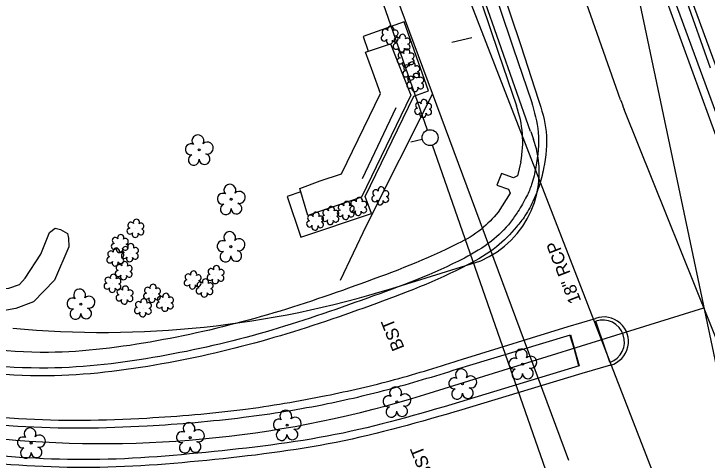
# Model space of a CAD drawing. Extents: x 1611576 to 1617186, y 899279 to 905462.
# Drawn here: x 1615954.6 to 1616172.8, y 904028.8 to 904169.2 of the extents above; entities that cross this region are included whole.
import ezdxf

# ---------------------------------------------------------------- set-up
doc = ezdxf.new("R2010")
doc.units = 0
for name, color, linetype in [('Default', 7, 'Continuous'), ('Exist Building', 7, 'Continuous'), ('Exist Horizontal Alignment', 7, 'Continuous'), ('Exist Other Culture Sign', 7, 'Continuous'), ('Exist Right of Way Line', 7, 'Continuous'), ('Exist Roads Curbs', 7, 'Continuous'), ('Exist Roads EOP', 7, 'Continuous'), ('Exist Roads EOP Other', 7, 'Continuous'), ('Exist Roads EOP Text', 7, 'Continuous'), ('Exist Structure Minor Pipes RCP 18 Inch', 7, 'Continuous'), ('Exist Structure Minor Pipes RCP 18 Inch Text', 7, 'Continuous'), ('Exist Vegetation Hedge Row', 7, 'Continuous'), ('Exist Vegetation Shrub CELL', 7, 'Continuous'), ('Exist Vegetation Tree CELL', 7, 'Continuous'), ('Prop 2 In Gas Line (St)', 7, 'Continuous'), ('Prop 6 In Gas Line (B2)', 7, 'Continuous'), ('Prop OH Pow Tel CATV Lines', 7, 'Continuous')]:
    doc.layers.add(name, color=color, linetype=linetype)

msp = doc.modelspace()

# ---------------------------------------------------------------- linework, layer by layer
at = {"layer": 'Default'}
msp.add_line((1616083.13, 904129.72), (1616079.48, 904128.88), dxfattribs=at)
msp.add_circle((1616085.57, 904130.27), 2.5, dxfattribs=at)
at = {"layer": 'Exist Building'}
msp.add_lwpolyline([(1616044.92, 904113.19), (1616040.56, 904111.77), (1616044.91, 904098.91), (1616067.1, 904106.39), (1616065.17, 904111.75), (1616080.46, 904143.28), (1616085.08, 904145.04), (1616077.43, 904166.71), (1616064.56, 904162.08), (1616066.07, 904157.45)], dxfattribs=at)
msp.add_lwpolyline([(1616044.58, 904114.3), (1616050.95, 904116.67), (1616057.75, 904118.84), (1616069.94, 904144.16), (1616067.54, 904150.85), (1616065.21, 904157.16), (1616073.11, 904159.81), (1616079.51, 904143.63), (1616063.97, 904111.54), (1616047.14, 904105.79)], close=True, dxfattribs=at)
at = {"layer": 'Exist Horizontal Alignment'}
for p, q in [((1616145.53, 904142.15), (1616079.93, 904328.43)), ((1616182.78, 904049.14), (1616146.69, 904139.07)), ((1616083.93, 904049.4), (1616171.72, 904076.69))]:
    msp.add_line(p, q, dxfattribs=at)
for centre, radius, start, end in [((1616217.59, 904167.52), 76.39, 199.4, 201.8667), ((1615982.39, 904376.05), 342.06, 264.7333, 287.2667)]:
    msp.add_arc(centre, radius, start, end, dxfattribs=at)
at = {"layer": 'Exist Other Culture Sign'}
for p, q in [((1616098.75, 904161.67), (1616092.45, 904160.16)), ((1616064.32, 904117.42), (1616074.94, 904139.75))]:
    msp.add_line(p, q, dxfattribs=at)
at = {"layer": 'Exist Right of Way Line'}
for p, q in [((1615887.44, 905426.15), (1616864.55, 900788.06)), ((1616173.83, 904152.11), (1616108.23, 904338.4)), ((1616117.23, 904132.18), (1616051.63, 904318.47)), ((1616073.54, 904082.82), (1616101.55, 904091.53))]:
    msp.add_line(p, q, dxfattribs=at)
for centre, radius, start, end in [((1616217.59, 904167.52), 106.39, 199.4, 200.861), ((1616089.66, 904119.39), 30.29, 293.1066, 19.7584), ((1615982.39, 904376.05), 307.06, 264.7333, 287.2667)]:
    msp.add_arc(centre, radius, start, end, dxfattribs=at)
at = {"layer": 'Exist Roads Curbs'}
msp.add_line((1616138.89, 904069.09), (1616137.75, 904072.51), dxfattribs=at)
for points in [[(1616117.86, 904294.32), (1616132.6, 904254.66), (1616147.03, 904215.59), (1616161.55, 904176.09), (1616175.82, 904137.25), (1616190.47, 904097.09), (1616204.98, 904057.33), (1616219.73, 904016.73), (1616233.88, 903976.63), (1616247.93, 903936.53), (1616261.75, 903896.6), (1616275.82, 903856.12), (1616289.5, 903816.57), (1616303.58, 903775.98), (1616318, 903734.48)], [(1616071.77, 904277.47), (1616085.18, 904237.58), (1616098.48, 904197.94), (1616111.7, 904158.5), (1616117.5, 904141.64)], [(1616142.11, 904059.56), (1616140.07, 904065.79), (1616138.89, 904069.09)], [(1616097, 904058.32), (1616129.81, 904068.25), (1616132.47, 904058.42), (1616097.28, 904047.76)]]:
    msp.add_lwpolyline(points, dxfattribs=at)
msp.add_ellipse((1616139.92, 904066.03), major_axis=(-0.95, 6.77), ratio=0.999591, start_param=3.328084, end_param=6.467483, dxfattribs=at)
for points in [[(1616117.5, 904141.64), (1616119.61, 904131.89), (1616118.86, 904120.99), (1616117.54, 904115.53), (1616115.97, 904111.79), (1616113.21, 904107), (1616110.89, 904103.69), (1616104.9, 904097.71), (1616096.36, 904092.38), (1616065.87, 904079.76), (1616033.72, 904069.07), (1616000.54, 904061.43), (1615965.3, 904057.76), (1615923.02, 904061.54), (1615919.54, 904062.14), (1615912.5, 904064.32), (1615906.06, 904068.89), (1615903.75, 904071.29), (1615901.6, 904074.35), (1615899.43, 904079.59), (1615898.96, 904087.08)], [(1615933.45, 904041.7), (1615955.8, 904039.5), (1615996.5, 904039.58), (1616026.82, 904042.27), (1616053.3, 904046.56), (1616074.92, 904051.74), (1616097, 904058.32)], [(1616097.28, 904047.76), (1616058.24, 904037.32), (1616017.59, 904031.47), (1615976.53, 904028.93), (1615936.16, 904031.22)]]:
    msp.add_spline(points, degree=3, dxfattribs=at)
at = {"layer": 'Exist Roads EOP'}
for p, q in [((1616129.02, 904070.85), (1616137.63, 904073.36)), ((1616095.78, 904060.53), (1616129.02, 904070.85)), ((1616142.39, 904058.67), (1616133.32, 904056.07)), ((1616133.32, 904056.07), (1616097.99, 904045.33))]:
    msp.add_line(p, q, dxfattribs=at)
for points in [[(1616115.61, 904293.45), (1616130.22, 904253.88), (1616144.71, 904214.78), (1616159.36, 904175.17), (1616173.54, 904136.33), (1616188.19, 904096.22), (1616202.56, 904056.51), (1616217.36, 904015.9), (1616231.52, 903975.89), (1616245.62, 903935.7), (1616259.38, 903895.73), (1616273.35, 903855.36), (1616287.12, 903815.79), (1616301.21, 903775.08), (1616315.66, 903733.58)], [(1616115.61, 904293.45), (1616130.22, 904253.88), (1616144.71, 904214.78), (1616159.36, 904175.17), (1616173.54, 904136.33), (1616188.19, 904096.22), (1616202.56, 904056.51), (1616217.36, 904015.9), (1616231.52, 903975.89), (1616245.62, 903935.7), (1616259.38, 903895.73), (1616273.35, 903855.36), (1616287.12, 903815.79)], [(1616074.22, 904278.19), (1616087.6, 904238.34), (1616100.83, 904198.88), (1616114.11, 904159.22), (1616119.62, 904142.34)]]:
    msp.add_lwpolyline(points, dxfattribs=at)
msp.add_ellipse((1616140.3, 904066.11), major_axis=(-0.84, 7.68), ratio=0.999926, start_param=3.305414, end_param=6.526886, dxfattribs=at)
for points in [[(1616119.62, 904142.34), (1616122.11, 904132.17), (1616121.32, 904120.53), (1616119.78, 904114.71), (1616118.22, 904110.85), (1616115.45, 904105.64), (1616112.79, 904102.18), (1616106.49, 904095.88), (1616097.4, 904090.23), (1616066.74, 904077.37), (1616034.38, 904066.74), (1616001.17, 904059.04), (1615965.14, 904055.31), (1615922.78, 904058.94), (1615919.06, 904059.46)], [(1615933.92, 904044.1), (1615956.01, 904041.93), (1615996.4, 904042.04), (1616026.66, 904044.72), (1616052.83, 904049.09), (1616074.4, 904054.13), (1616095.78, 904060.53)], [(1616097.99, 904045.33), (1616058.52, 904034.87), (1616017.88, 904028.96), (1615976.43, 904026.45), (1615935.89, 904028.72)]]:
    msp.add_spline(points, degree=3, dxfattribs=at)
at = {"layer": 'Exist Roads EOP Other'}
for points in [[(1616122.43, 904296.46), (1616137.34, 904256.3), (1616151.63, 904217.58), (1616166.45, 904177.4), (1616180.52, 904139.04), (1616195.16, 904098.73), (1616209.58, 904059.11), (1616224.45, 904018.46), (1616238.58, 903978.47), (1616252.68, 903938.24), (1616266.45, 903898.41), (1616280.47, 903857.78), (1616294.14, 903818.38), (1616308.3, 903777.63), (1616322.66, 903736.35)], [(1616066.97, 904276.15), (1616080.53, 904235.92), (1616093.82, 904196.35), (1616107.14, 904156.8), (1616112.75, 904140.23)], [(1616114.1, 904122.64), (1616113.07, 904118.2), (1616111.78, 904117.65), (1616108.09, 904118.96), (1616106.56, 904115.31), (1616110.27, 904114.03), (1616110.83, 904112.77), (1616106.96, 904106.8)], [(1616132.43, 904058.48), (1616131.01, 904063.55), (1616129.59, 904068.21)]]:
    msp.add_lwpolyline(points, dxfattribs=at)
msp.add_ellipse((1616082.32, 904129.04), major_axis=(32.26, -3.18), ratio=0.999878, start_param=6.182795, end_param=6.733904, dxfattribs=at)
msp.add_spline([(1616106.96, 904106.8), (1616101.73, 904101.46), (1616094.3, 904096.91), (1616063.81, 904084.29), (1616032.43, 904073.94), (1615999.62, 904066.32), (1615965.45, 904062.7), (1615923.72, 904066.51), (1615907.72, 904068.75)], degree=3, dxfattribs=at)
at = {"layer": 'Exist Structure Minor Pipes RCP 18 Inch'}
msp.add_line((1616084.02, 904209.5), (1616168.38, 903992.15), dxfattribs=at)
msp.add_line((1616084.02, 904209.5), (1616168.38, 903992.15), dxfattribs=at)
at = {"layer": 'Exist Vegetation Hedge Row'}
msp.add_lwpolyline([(1615938.23, 904083.52), (1615946.62, 904082.36), (1615953, 904082.91), (1615956.38, 904084.07), (1615958.13, 904086.09), (1615963.08, 904093.6), (1615965.84, 904100.45), (1615967.6, 904101.8), (1615969.21, 904101.4), (1615971.43, 904100.05), (1615971.79, 904098.68), (1615971.84, 904095.94), (1615967.35, 904085.46), (1615960.72, 904078.64), (1615955.21, 904076.48), (1615948.65, 904075.36), (1615941.25, 904075.57), (1615919.09, 904078.95)], dxfattribs=at)
at = {"layer": 'Exist Vegetation Shrub CELL'}
for p, q in [((1616072.93, 904162.31), (1616072.93, 904162.31)), ((1616076.69, 904159.74), (1616076.69, 904159.74)), ((1616078, 904155.09), (1616078, 904155.09)), ((1616079.71, 904151.04), (1616079.71, 904151.04)), ((1616080.97, 904147.46), (1616080.97, 904147.46)), ((1616083.47, 904139.24), (1616083.47, 904139.24)), ((1616069.98, 904111.76), (1616069.98, 904111.76)), ((1616063.06, 904108.42), (1616063.06, 904108.42)), ((1616059.12, 904107.15), (1616059.12, 904107.15)), ((1616054.28, 904105.56), (1616054.28, 904105.56)), ((1616049.48, 904103.79), (1616049.48, 904103.79)), ((1615992.92, 904101.56), (1615992.92, 904101.56)), ((1615988, 904096.73), (1615988, 904096.73)), ((1615991.17, 904093.89), (1615991.17, 904093.89)), ((1615986.58, 904092.51), (1615986.58, 904092.51)), ((1615989.24, 904088.21), (1615989.24, 904088.21)), ((1616018.13, 904086.98), (1616018.13, 904086.98)), ((1615985.7, 904084.24), (1615985.7, 904084.24)), ((1616010.92, 904085.29), (1616010.92, 904085.29)), ((1616014.67, 904082.77), (1616014.67, 904082.77)), ((1615989.48, 904080.54), (1615989.48, 904080.54)), ((1615998.16, 904081.1), (1615998.16, 904081.1)), ((1616002.21, 904078.27), (1616002.21, 904078.27)), ((1615995.27, 904076.55), (1615995.27, 904076.55))]:
    msp.add_line(p, q, dxfattribs=at)
for centre, radius, start, end in [((1616073.16, 904164.35), 0.99, 334.8391, 200.4717), ((1616071.45, 904163.43), 0.968, 35.8908, 245.4216), ((1616074.61, 904163.18), 0.929, 284.4567, 126.0861), ((1616076.92, 904161.78), 0.99, 334.8391, 200.4717), ((1616071.13, 904161.6), 0.955, 95.1099, 327.9534), ((1616072.8, 904160.62), 0.984, 151.2797, 21.387), ((1616074.57, 904161.38), 0.937, 204.9913, 73.4601), ((1616075.21, 904160.86), 0.968, 35.8908, 245.4216), ((1616078.36, 904160.61), 0.929, 284.4567, 126.0861), ((1616074.89, 904159.03), 0.955, 95.1099, 327.9534), ((1616076.56, 904158.05), 0.984, 151.2797, 21.387), ((1616078.33, 904158.81), 0.937, 204.9913, 73.4601), ((1616076.52, 904156.22), 0.968, 35.8908, 245.4216), ((1616078.23, 904157.13), 0.99, 334.8391, 200.4717), ((1616079.67, 904155.96), 0.929, 284.4567, 126.0861), ((1616076.2, 904154.39), 0.955, 95.1099, 327.9534), ((1616079.64, 904154.16), 0.937, 204.9913, 73.4601), ((1616079.94, 904153.08), 0.99, 334.8391, 200.4717), ((1616077.87, 904153.41), 0.984, 151.2797, 21.387), ((1616078.23, 904152.17), 0.968, 35.8908, 245.4216), ((1616081.39, 904151.91), 0.929, 284.4567, 126.0861), ((1616077.91, 904150.34), 0.955, 95.1099, 327.9534), ((1616079.59, 904149.36), 0.984, 151.2797, 21.387), ((1616081.2, 904149.5), 0.99, 334.8391, 200.4717), ((1616081.35, 904150.11), 0.937, 204.9913, 73.4601), ((1616079.17, 904146.76), 0.955, 95.1099, 327.9534), ((1616079.48, 904148.59), 0.968, 35.8908, 245.4216), ((1616082.64, 904148.33), 0.929, 284.4567, 126.0861), ((1616080.84, 904145.78), 0.984, 151.2797, 21.387), ((1616082.6, 904146.54), 0.937, 204.9913, 73.4601), ((1616081.99, 904140.37), 0.968, 35.8908, 245.4216), ((1616083.7, 904141.28), 0.99, 334.8391, 200.4717), ((1616085.14, 904140.11), 0.929, 284.4567, 126.0861), ((1616081.67, 904138.54), 0.955, 95.1099, 327.9534), ((1616085.11, 904138.31), 0.937, 204.9913, 73.4601), ((1616083.34, 904137.56), 0.984, 151.2797, 21.387), ((1616070.21, 904113.8), 0.99, 334.8391, 200.4717), ((1616068.5, 904112.88), 0.968, 35.8908, 245.4216), ((1616071.65, 904112.62), 0.929, 284.4567, 126.0861), ((1616061.57, 904109.55), 0.968, 35.8908, 245.4216), ((1616063.29, 904110.46), 0.99, 334.8391, 200.4717), ((1616068.18, 904111.05), 0.955, 95.1099, 327.9534), ((1616069.85, 904110.07), 0.984, 151.2797, 21.387), ((1616071.62, 904110.83), 0.937, 204.9913, 73.4601), ((1616054.5, 904107.6), 0.99, 334.8391, 200.4717), ((1616057.64, 904108.28), 0.968, 35.8908, 245.4216), ((1616059.35, 904109.19), 0.99, 334.8391, 200.4717), ((1616060.8, 904108.02), 0.929, 284.4567, 126.0861), ((1616061.26, 904107.71), 0.955, 95.1099, 327.9534), ((1616064.69, 904107.49), 0.937, 204.9913, 73.4601), ((1616064.73, 904109.29), 0.929, 284.4567, 126.0861), ((1616049.71, 904105.83), 0.99, 334.8391, 200.4717), ((1616052.79, 904106.69), 0.968, 35.8908, 245.4216), ((1616055.95, 904106.43), 0.929, 284.4567, 126.0861), ((1616057.32, 904106.45), 0.955, 95.1099, 327.9534), ((1616060.76, 904106.22), 0.937, 204.9913, 73.4601), ((1616062.93, 904106.73), 0.984, 151.2797, 21.387), ((1615993.15, 904103.6), 0.99, 334.8391, 200.4717), ((1616047.68, 904103.09), 0.955, 95.1099, 327.9534), ((1616048, 904104.92), 0.968, 35.8908, 245.4216), ((1616051.15, 904104.66), 0.929, 284.4567, 126.0861), ((1616052.48, 904104.85), 0.955, 95.1099, 327.9534), ((1616054.15, 904103.88), 0.984, 151.2797, 21.387), ((1616055.91, 904104.63), 0.937, 204.9913, 73.4601), ((1616059, 904105.47), 0.984, 151.2797, 21.387), ((1615991.12, 904100.85), 0.955, 95.1099, 327.9534), ((1615991.44, 904102.68), 0.968, 35.8908, 245.4216), ((1615994.59, 904102.43), 0.929, 284.4567, 126.0861), ((1616049.35, 904102.11), 0.984, 151.2797, 21.387), ((1616051.11, 904102.86), 0.937, 204.9913, 73.4601), ((1615988.23, 904098.77), 0.99, 334.8391, 200.4717), ((1615992.79, 904099.87), 0.984, 151.2797, 21.387), ((1615994.56, 904100.63), 0.937, 204.9913, 73.4601), ((1615986.52, 904097.86), 0.968, 35.8908, 245.4216), ((1615989.68, 904097.6), 0.929, 284.4567, 126.0861), ((1615986.2, 904096.03), 0.955, 95.1099, 327.9534), ((1615986.81, 904094.55), 0.99, 334.8391, 200.4717), ((1615987.88, 904095.05), 0.984, 151.2797, 21.387), ((1615989.69, 904095.02), 0.968, 35.8908, 245.4216), ((1615989.64, 904095.8), 0.937, 204.9913, 73.4601), ((1615991.4, 904095.93), 0.99, 334.8391, 200.4717), ((1615992.85, 904094.76), 0.929, 284.4567, 126.0861), ((1615985.1, 904093.64), 0.968, 35.8908, 245.4216), ((1615988.25, 904093.38), 0.929, 284.4567, 126.0861), ((1615989.37, 904093.19), 0.955, 95.1099, 327.9534), ((1615992.81, 904092.96), 0.937, 204.9913, 73.4601), ((1615984.78, 904091.81), 0.955, 95.1099, 327.9534), ((1615986.45, 904090.83), 0.984, 151.2797, 21.387), ((1615988.22, 904091.58), 0.937, 204.9913, 73.4601), ((1615989.47, 904090.25), 0.99, 334.8391, 200.4717), ((1615991.05, 904092.21), 0.984, 151.2797, 21.387), ((1615987.75, 904089.34), 0.968, 35.8908, 245.4216), ((1615990.91, 904089.08), 0.929, 284.4567, 126.0861), ((1616016.65, 904088.11), 0.968, 35.8908, 245.4216), ((1616018.36, 904089.02), 0.99, 334.8391, 200.4717), ((1616019.8, 904087.85), 0.929, 284.4567, 126.0861), ((1615985.93, 904086.28), 0.99, 334.8391, 200.4717), ((1615987.44, 904087.51), 0.955, 95.1099, 327.9534), ((1615989.11, 904086.53), 0.984, 151.2797, 21.387), ((1615990.87, 904087.29), 0.937, 204.9913, 73.4601), ((1616009.43, 904086.42), 0.968, 35.8908, 245.4216), ((1616011.14, 904087.33), 0.99, 334.8391, 200.4717), ((1616012.59, 904086.16), 0.929, 284.4567, 126.0861), ((1616016.33, 904086.27), 0.955, 95.1099, 327.9534), ((1616019.77, 904086.05), 0.937, 204.9913, 73.4601), ((1615983.9, 904083.54), 0.955, 95.1099, 327.9534), ((1615984.22, 904085.37), 0.968, 35.8908, 245.4216), ((1615987.34, 904083.31), 0.937, 204.9913, 73.4601), ((1615987.37, 904085.11), 0.929, 284.4567, 126.0861), ((1616009.12, 904084.59), 0.955, 95.1099, 327.9534), ((1616012.55, 904084.36), 0.937, 204.9913, 73.4601), ((1616013.19, 904083.89), 0.968, 35.8908, 245.4216), ((1616014.9, 904084.81), 0.99, 334.8391, 200.4717), ((1616016.34, 904083.63), 0.929, 284.4567, 126.0861), ((1616018, 904085.3), 0.984, 151.2797, 21.387), ((1615985.57, 904082.56), 0.984, 151.2797, 21.387), ((1615988, 904081.67), 0.968, 35.8908, 245.4216), ((1615989.71, 904082.58), 0.99, 334.8391, 200.4717), ((1615991.16, 904081.41), 0.929, 284.4567, 126.0861), ((1615996.68, 904082.22), 0.968, 35.8908, 245.4216), ((1615998.39, 904083.14), 0.99, 334.8391, 200.4717), ((1615999.83, 904081.97), 0.929, 284.4567, 126.0861), ((1616010.79, 904083.61), 0.984, 151.2797, 21.387), ((1616012.87, 904082.06), 0.955, 95.1099, 327.9534), ((1616016.31, 904081.84), 0.937, 204.9913, 73.4601), ((1615987.68, 904079.84), 0.955, 95.1099, 327.9534), ((1615991.12, 904079.61), 0.937, 204.9913, 73.4601), ((1615996.36, 904080.39), 0.955, 95.1099, 327.9534), ((1615998.03, 904079.41), 0.984, 151.2797, 21.387), ((1615999.8, 904080.17), 0.937, 204.9913, 73.4601), ((1616000.73, 904079.4), 0.968, 35.8908, 245.4216), ((1616002.44, 904080.31), 0.99, 334.8391, 200.4717), ((1616003.89, 904079.14), 0.929, 284.4567, 126.0861), ((1616014.54, 904081.08), 0.984, 151.2797, 21.387), ((1615989.35, 904078.86), 0.984, 151.2797, 21.387), ((1615993.79, 904077.68), 0.968, 35.8908, 245.4216), ((1615995.5, 904078.59), 0.99, 334.8391, 200.4717), ((1615996.94, 904077.42), 0.929, 284.4567, 126.0861), ((1616000.41, 904077.57), 0.955, 95.1099, 327.9534), ((1616003.85, 904077.34), 0.937, 204.9913, 73.4601), ((1615993.47, 904075.85), 0.955, 95.1099, 327.9534), ((1615996.91, 904075.62), 0.937, 204.9913, 73.4601), ((1616002.09, 904076.59), 0.984, 151.2797, 21.387), ((1615995.14, 904074.87), 0.984, 151.2797, 21.387)]:
    msp.add_arc(centre, radius, start, end, dxfattribs=at)
at = {"layer": 'Exist Vegetation Tree CELL'}
for p, q in [((1616012.89, 904126.4), (1616012.89, 904126.4)), ((1616022.95, 904110.86), (1616022.95, 904110.86)), ((1616022.87, 904095.96), (1616022.87, 904095.96)), ((1615975.64, 904077.89), (1615975.64, 904077.89)), ((1616114.71, 904059.01), (1616114.71, 904059.01)), ((1616095.8, 904052.78), (1616095.8, 904052.78)), ((1616075.09, 904047.11), (1616075.09, 904047.11)), ((1616040.57, 904039.79), (1616040.57, 904039.79)), ((1615960.05, 904034.17), (1615960.05, 904034.17)), ((1616010.09, 904035.86), (1616010.09, 904035.86))]:
    msp.add_line(p, q, dxfattribs=at)
for centre in [(1616012.89, 904126.4), (1616022.95, 904110.86), (1616022.87, 904095.96), (1615975.64, 904077.89), (1616114.71, 904059.01), (1616095.8, 904052.78), (1616075.09, 904047.11), (1616040.57, 904039.79), (1616010.09, 904035.86), (1615960.05, 904034.17)]:
    msp.add_circle(centre, 0.326, dxfattribs=at)
for centre, radius, start, end in [((1616012.5, 904129.28), 1.86, 330.1651, 219.7134), ((1616010.28, 904126.56), 1.73, 62.6636, 279.3457), ((1616015.44, 904126.99), 1.9, 257.1011, 134.1999), ((1616011.18, 904123.28), 1.69, 111.5671, 6.231), ((1616014.56, 904123.51), 1.7, 181.2822, 74.56), ((1616022.57, 904113.73), 1.86, 330.1651, 219.7134), ((1616020.35, 904111.01), 1.73, 62.6636, 279.3457), ((1616025.5, 904111.44), 1.9, 257.1011, 134.1999), ((1616021.25, 904107.73), 1.69, 111.5671, 6.231), ((1616024.62, 904107.96), 1.7, 181.2822, 74.56), ((1616022.49, 904098.83), 1.86, 330.1651, 219.7134), ((1616020.27, 904096.11), 1.73, 62.6636, 279.3457), ((1616025.42, 904096.54), 1.9, 257.1011, 134.1999), ((1616021.17, 904092.83), 1.69, 111.5671, 6.231), ((1616024.55, 904093.06), 1.7, 181.2822, 74.56), ((1615975.26, 904080.77), 1.86, 330.1651, 219.7134), ((1615978.19, 904078.48), 1.9, 257.1011, 134.1999), ((1615973.04, 904078.05), 1.73, 62.6636, 279.3457), ((1615973.94, 904074.77), 1.69, 111.5671, 6.231), ((1615977.31, 904074.99), 1.7, 181.2822, 74.56), ((1616114.32, 904061.88), 1.86, 330.1651, 219.7134), ((1616112.1, 904059.16), 1.73, 62.6636, 279.3457), ((1616117.26, 904059.59), 1.9, 257.1011, 134.1999), ((1616095.41, 904055.65), 1.86, 330.1651, 219.7134), ((1616113, 904055.89), 1.69, 111.5671, 6.231), ((1616116.38, 904056.11), 1.7, 181.2822, 74.56), ((1616093.19, 904052.93), 1.73, 62.6636, 279.3457), ((1616098.35, 904053.37), 1.9, 257.1011, 134.1999), ((1616074.71, 904049.98), 1.86, 330.1651, 219.7134), ((1616097.47, 904049.88), 1.7, 181.2822, 74.56), ((1616077.64, 904047.7), 1.9, 257.1011, 134.1999), ((1616094.09, 904049.66), 1.69, 111.5671, 6.231), ((1616072.48, 904047.27), 1.73, 62.6636, 279.3457), ((1616073.39, 904043.99), 1.69, 111.5671, 6.231), ((1616076.76, 904044.21), 1.7, 181.2822, 74.56), ((1616040.18, 904042.66), 1.86, 330.1651, 219.7134), ((1616009.7, 904038.73), 1.86, 330.1651, 219.7134), ((1616037.96, 904039.94), 1.73, 62.6636, 279.3457), ((1616043.11, 904040.38), 1.9, 257.1011, 134.1999), ((1615959.67, 904037.05), 1.86, 330.1651, 219.7134), ((1616042.24, 904036.89), 1.7, 181.2822, 74.56), ((1615962.6, 904034.76), 1.9, 257.1011, 134.1999), ((1616007.48, 904036.01), 1.73, 62.6636, 279.3457), ((1616012.64, 904036.44), 1.9, 257.1011, 134.1999), ((1616038.86, 904036.67), 1.69, 111.5671, 6.231), ((1615957.45, 904034.33), 1.73, 62.6636, 279.3457), ((1616008.38, 904032.73), 1.69, 111.5671, 6.231), ((1616011.76, 904032.96), 1.7, 181.2822, 74.56), ((1615958.35, 904031.05), 1.69, 111.5671, 6.231), ((1615961.72, 904031.27), 1.7, 181.2822, 74.56)]:
    msp.add_arc(centre, radius, start, end, dxfattribs=at)
at = {"layer": 'Prop 2 In Gas Line (St)'}
for p, q in [((1616086.38, 904144.09), (1616065.49, 904102.5)), ((1616065.49, 904102.5), (1616057.32, 904085.33))]:
    msp.add_line(p, q, dxfattribs=at)
at = {"layer": 'Prop 6 In Gas Line (B2)'}
msp.add_line((1616129.25, 904028.65), (1616069.92, 904188.28), dxfattribs=at)
at = {"layer": 'Prop OH Pow Tel CATV Lines'}
for p, q in [((1616084.75, 904132.64), (1616001.87, 904370.71)), ((1616155.55, 903929.25), (1616086.39, 904127.91))]:
    msp.add_line(p, q, dxfattribs=at)

# ---------------------------------------------------------------- texts
at = {"layer": 'Exist Roads EOP Text'}
for p in [(1616077.59, 904064.14), (1616086.78, 904024.05)]:
    msp.add_text('BST', height=4, rotation=111.8667, dxfattribs=at).set_placement(p)
at = {"layer": 'Exist Structure Minor Pipes RCP 18 Inch Text'}
msp.add_text('18" RCP', height=4, rotation=111.2126, dxfattribs=at).set_placement((1616133.22, 904078.91))

doc.saveas('drawing.dxf')
